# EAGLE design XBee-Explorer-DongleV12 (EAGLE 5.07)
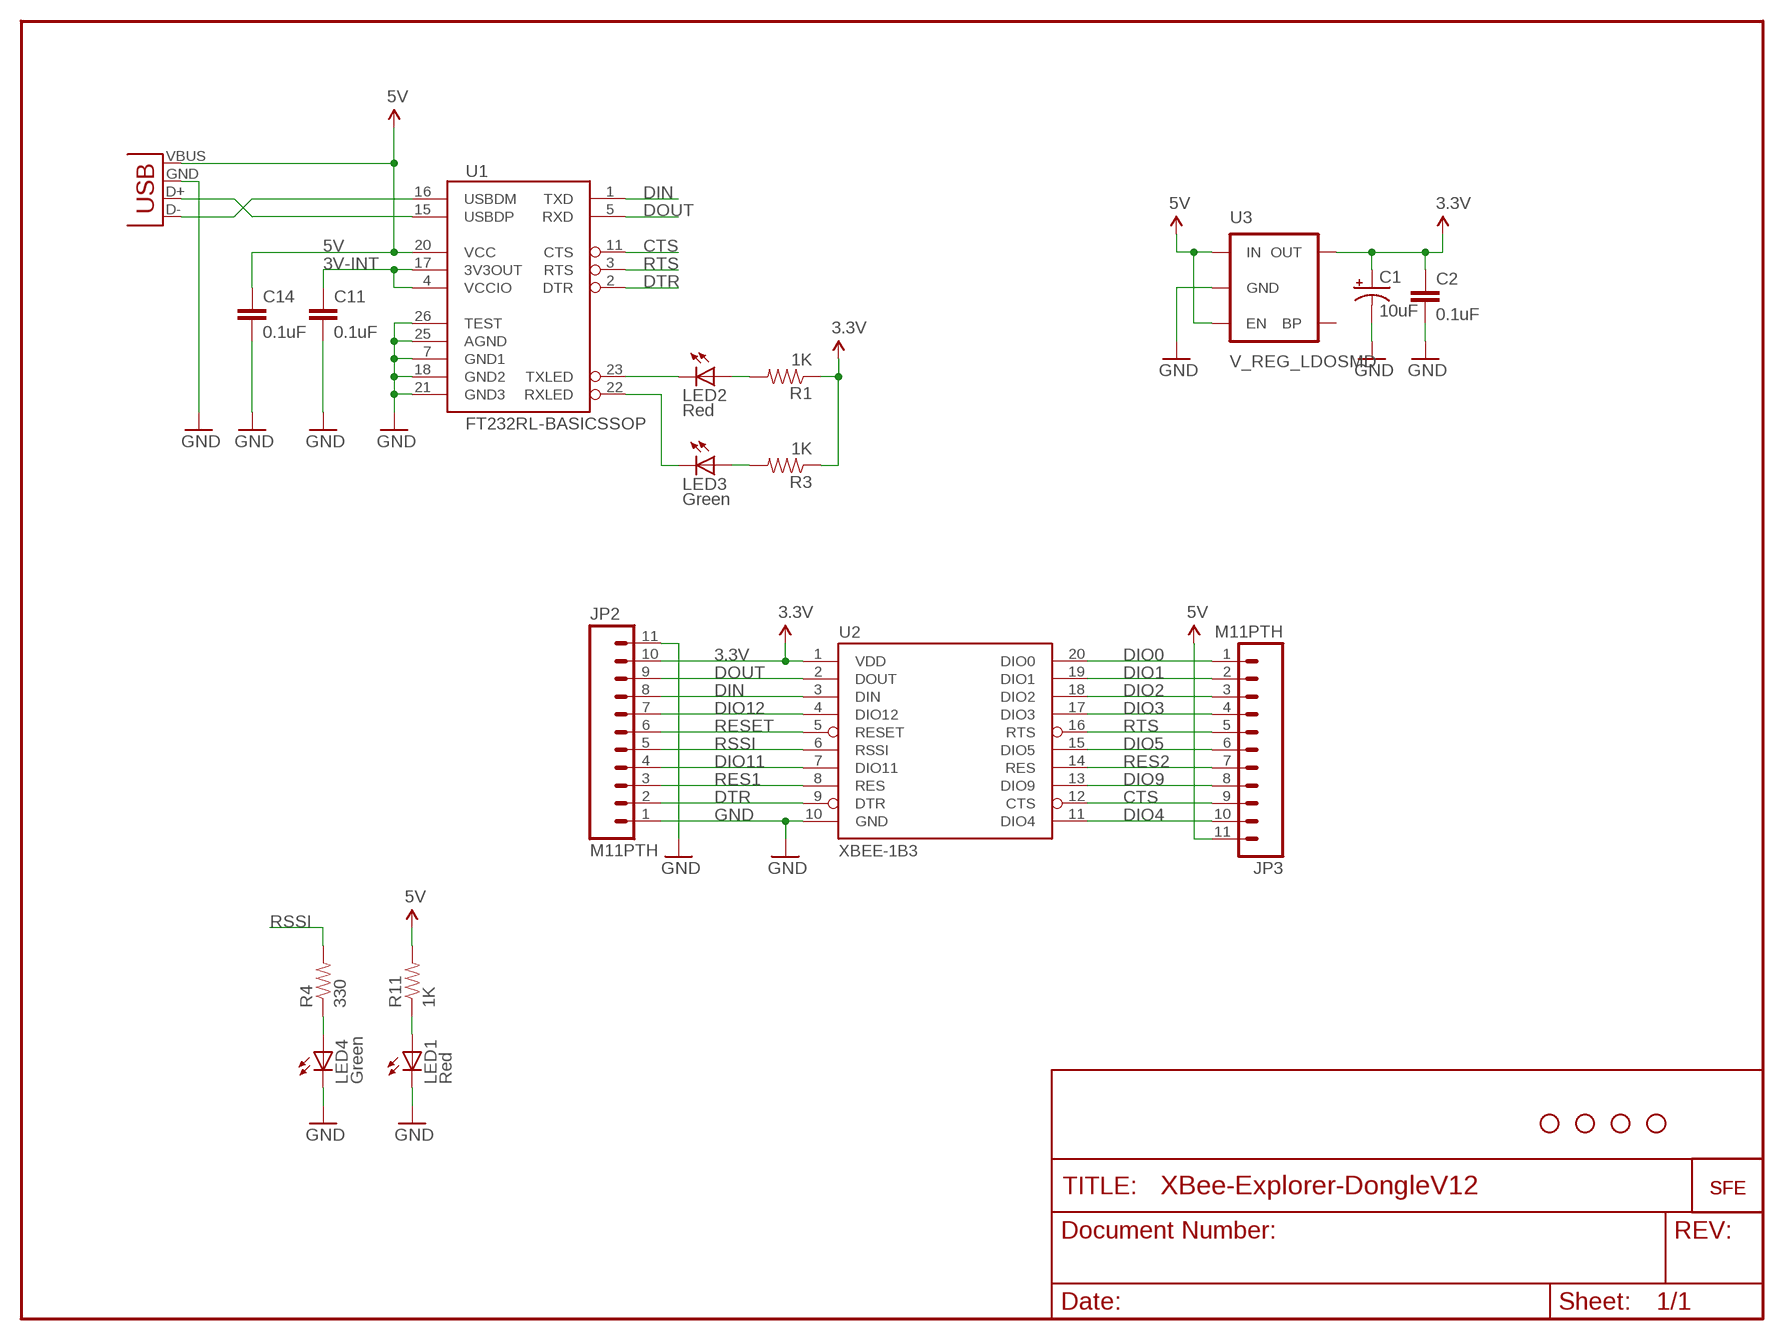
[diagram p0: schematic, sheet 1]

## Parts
C1  10uF  CAP_POL1206  [EIA3216]
C2  0.1uF  CAP0402-CAP  [0402-CAP]
C11  0.1uF  CAP0402-CAP  [0402-CAP]
C14  0.1uF  CAP0402-CAP  [0402-CAP]
JP2  M11PTH  [1X11]
JP3  M11PTH  [1X11]
LED1  Red  LED0603  [LED-0603]
LED2  Red  LED0603  [LED-0603]
LED3  Green  LED0603  [LED-0603]
LED4  Green  LED0603  [LED-0603]
R1  1K  RESISTOR  [0805]
R3  1K  RESISTOR  [0805]
R4  330  RESISTOR0603-RES  [0603-RES]
R11  1K  RESISTOR0603-RES  [0603-RES]
U1  FT232RL-BASICSSOP  [SSOP28DB]
U2  XBEE-1B3  [XBEE-SMD]
U3  V_REG_LDOSMD  [SOT23-5]
U$1  LOGO-SFESK  [SFE-LOGO-FLAME]
U$4  LOGO-SFENEW  [SFE-NEW-WEBLOGO]
U$5  STAND-OFF  [STAND-OFF]
U$9  STAND-OFF  [STAND-OFF]
U$10  STAND-OFF  [STAND-OFF]
U$11  STAND-OFF  [STAND-OFF]
X2  USB-A-H  [USB-A-H]

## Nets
3.3V [vcc]: C1.A(+) C2.1 JP2.10 R1.1 R3.1 U2.1(VDD) U3.5(OUT)
3V-INT [vcc]: C11.1 U1.4(VCCIO) U1.17(3V3OUT)
5V [vcc]: C14.1 JP3.11 R11.2 U1.20(VCC) U3.1(IN) U3.3(EN) X2.VBUS(GND)
CTS: JP3.9 U1.11(CTS) U2.12(CTS)
DIN: JP2.8 U1.1(TXD) U2.3(DIN)
DIO0: JP3.1 U2.20(DIO0)
DIO1: JP3.2 U2.19(DIO1)
DIO2: JP3.3 U2.18(DIO2)
DIO3: JP3.4 U2.17(DIO3)
DIO4: JP3.10 U2.11(DIO4)
DIO5: JP3.6 U2.15(DIO5)
DIO9: JP3.8 U2.13(DIO9)
DIO11: JP2.4 U2.7(DIO11)
DIO12: JP2.7 U2.4(DIO12)
DOUT: JP2.9 U1.5(RXD) U2.2(DOUT)
DTR: JP2.2 U1.2(DTR) U2.9(DTR)
GND [vcc]: C1.C(-) C2.2 C11.2 C14.2 JP2.1 JP2.11 LED1.C LED4.C U1.7(GND1) U1.18(GND2) U1.21(GND3) U1.25(AGND) U1.26(TEST) U2.10(GND) U3.2(GND) X2.GND(VBUS)
N$1: LED2.A R1.2
N$2: LED4.A R4.1
N$3: U1.16(USBDM) X2.D-(D+)
N$4: LED3.A R3.2
N$7: U1.15(USBDP) X2.D+(D-)
N$38: LED1.A R11.1
RES1: JP2.3 U2.8(RES)
RES2: JP3.7 U2.14(RES)
RESET: JP2.6 U2.5(RESET)
RSSI: JP2.5 R4.2 U2.6(RSSI)
RTS: JP3.5 U1.3(RTS) U2.16(RTS)
RXLED: LED3.C U1.22(RXLED)
TXLED: LED2.C U1.23(TXLED)
Unconnected: U3.4(BP)

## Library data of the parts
C1 = SparkFun:CAP_POL: Capacitor Polarized
C2 C11 C14 = SparkFun:CAP: Capacitor
JP2 JP3 = SparkFun:M11: Header 11 Standard 11-pin 0.1" header. Use with straight break away headers (SKU : PRT-00116), right angle break away headers (PRT-00553), swiss pins (PRT-00743), machine pins (PRT-00117), and female headers (PRT-00115).
LED1-LED4 = SparkFun:LED: LEDs
R1 R3 R4 R11 = SparkFun:RESISTOR: Resistor
U1 = SparkFun:FT232RL-BASIC: USB UART This is the simplified version of the FT232RL unit. Only what you need, nothing you don't. Spark Fun Electronics SKU : COM-00650
U2 = SparkFun:XBEE-1
U3 = SparkFun:V_REG_LDO: Voltage Regulator LDO Standard 150mA LDO voltage regulator in SOT-23 layout. Micrel part MIC5205. BP (by-pass) pin is used to lower output noise with 470pF cap.
U$1 U$4 = SparkFun:LOGO-SFE: Spark Fun Electronics PCB Logo
U$5 U$9-U$11 = SparkFun:STAND-OFF: Stand Off
X2 = SparkFun:USB: USB Connectors USB-B-PTH is fully proven SKU : PRT-00139 USB-miniB is fully proven SKU : PRT-00587 USB-A-PCB is untested. USB-A-H is throughly reviewed, but untested. Spark Fun Electronics SKU : PRT-00437 USB-B-SMT is throughly reviewed, but untested. Needs silkscreen touching up. USB-A-S has not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

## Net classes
0 default: width 0.203 mm
1 vcc: width 0.254 mm
2 gnd: width 0.254 mm

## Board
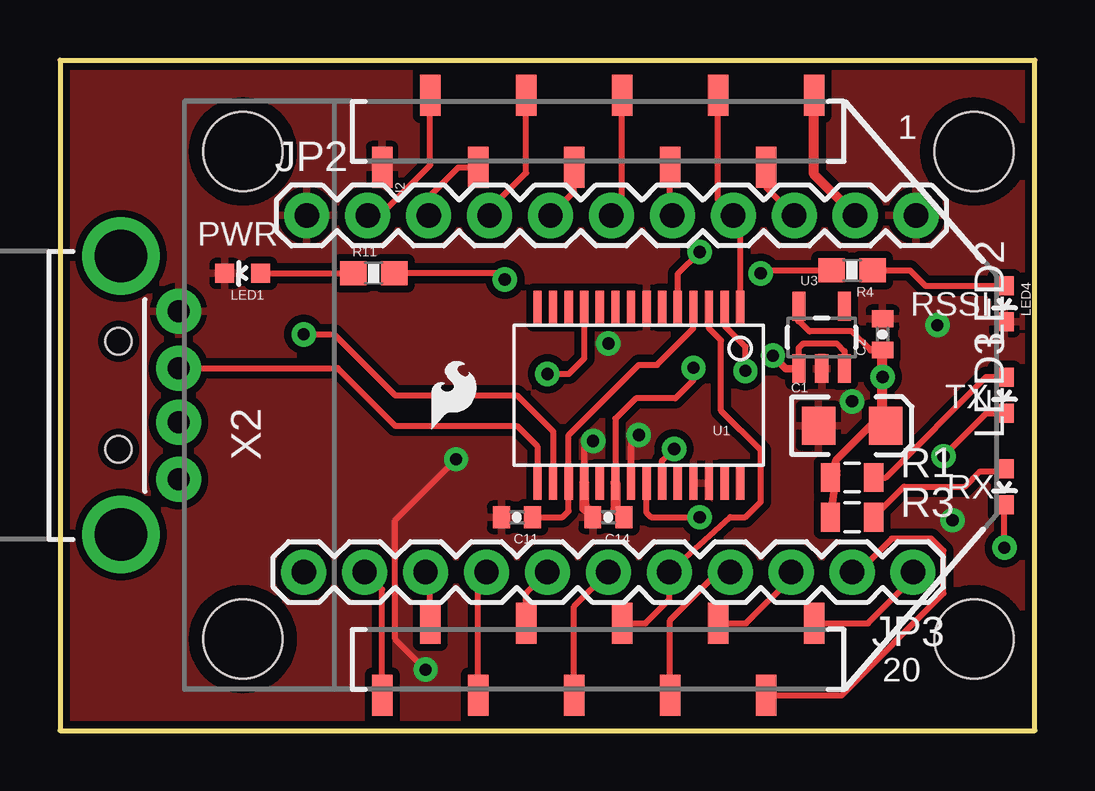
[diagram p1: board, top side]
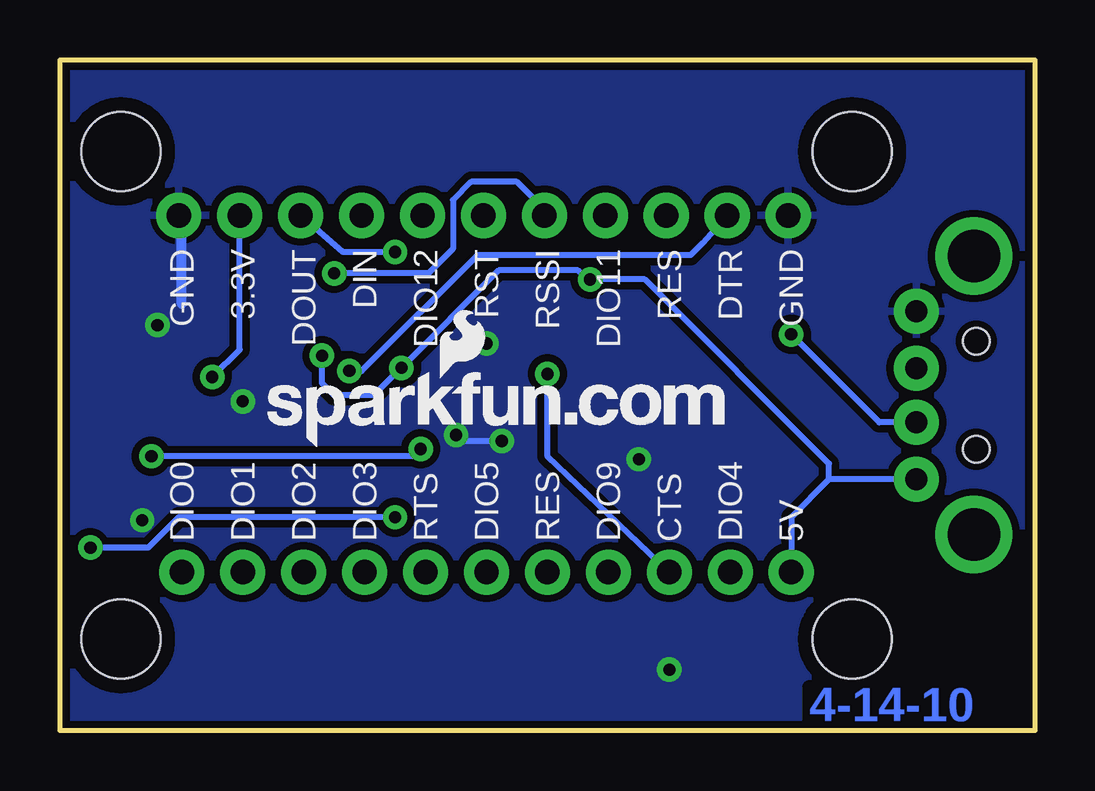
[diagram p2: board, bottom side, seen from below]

Size 40.64 x 27.94 mm. Coordinates in mm from the lower left corner, seen from the top.
Outline: 40.64,0 40.64,27.94 0,27.94 0,0 40.64,0
Copper layers (1*16): Top 0.035mm / dielectric 1.5mm / Bottom 0.035mm
Design rules "SparkFun": minimum track width 8mil, minimum drill 20mil, track to track 8mil, track to pad 8mil, pad to pad 8mil, via to via 8mil, smd to smd 8mil, copper to edge 9mil, drill to drill 8mil, minimum pad ring 12mil, minimum via ring 10mil, stop-mask expansion 4mil, vias tented up to drill 20mil, thermal gap 10mil

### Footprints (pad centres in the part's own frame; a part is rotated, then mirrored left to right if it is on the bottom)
EIA3216 = smd 1.4 x 1.6: A 1.4,0; C -1.4,0
0402-CAP = smd 0.7 x 0.9: 1 -0.65,0; 2 0.65,0
1X11 = drill 1.016 pad 1.88 round: 1 0,0; 2 2.54,0; 3 5.08,0; 4 7.62,0; 5 10.16,0; 6 12.7,0; 7 15.24,0; 8 17.78,0; 9 20.32,0; 10 22.86,0; 11 25.4,0
LED-0603 = smd 0.8 x 0.8: A 0,-0.75; C 0,0.75
0805 = smd 0.8 x 1.2: 1 -0.9,0; 2 0.9,0
0603-RES = smd 1.1 x 1: 1 -0.85,0; 2 0.85,0
SSOP28DB = smd 0.348 x 1.397: 1 -4.225,-3.656; 2 -3.575,-3.656; 3 -2.925,-3.656; 4 -2.275,-3.656; 5 -1.625,-3.656; 6 -0.975,-3.656; 7 -0.325,-3.656; 8 0.325,-3.656; 9 0.975,-3.656; 10 1.625,-3.656; 11 2.275,-3.656; 12 2.925,-3.656; 13 3.575,-3.656; 14 4.225,-3.656; 15 4.225,3.656; 16 3.575,3.656; 17 2.925,3.656; 18 2.275,3.656; 19 1.625,3.656; 20 0.975,3.656; 21 0.325,3.656; 22 -0.325,3.656; 23 -0.975,3.656; 24 -1.625,3.656; 25 -2.275,3.656; 26 -2.925,3.656; 27 -3.575,3.656; 28 -4.225,3.656
XBEE-SMD = smd 1.7 x 0.85: 1 -12.5,20; 2 -9.5,18; 3 -12.5,16; 4 -9.5,14; 5 -12.5,12; 6 -9.5,10; 7 -12.5,8; 8 -9.5,6; 9 -12.5,4; 10 -9.5,2; 11 12.5,2; 12 9.5,4; 13 12.5,6; 14 9.5,8; 15 12.5,10; 16 9.5,12; 17 12.5,14; 18 9.5,16; 19 12.5,18; 20 9.5,20
SOT23-5 = smd 0.55 x 1.2: 1 -0.95,-1.3; 2 0,-1.3; 3 0.95,-1.3; 4 0.95,1.3; 5 -0.95,1.3
STAND-OFF = hole 3.302: 0,0
USB-A-H = drill 0.914 pad 1.88 round: D+ 2.4,1.127; D- 2.4,-1.127; GND 2.4,3.5; VBUS 2.4,-3.5 | drill 2.2 round: GND@1 0,5.8; GND@2 0,-5.8 | hole 1.1: -0.1,2.25; -0.1,-2.25

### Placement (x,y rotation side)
C1  33.02,12.7 0 top
C2  34.29,16.51 90 top
C11  19.05,8.89 180 top
C14  22.86,8.89 180 top
JP2  10.29,21.46 0 top
JP3  35.56,6.6 180 top
LED1  7.62,19.05 90 top
LED2  39.37,13.97 180 top
LED3  39.37,10.16 180 top
LED4  39.37,17.78 180 top
R1  33.02,10.54 0 top
R3  33.02,8.89 0 top
R4  33.02,19.18 180 top
R11  13.08,19.05 0 top
U1  24.13,13.97 180 top
U2  11.43,13.97 270 top
U3  31.75,16.38 0 top
U$1  15.49,12.57 0 top
U$4  32,11.81 0 bottom
U$5  7.62,3.81 0 top
U$9  7.62,24.13 0 top
U$10  38.1,24.13 0 top
U$11  38.1,3.81 0 top
X2  2.54,13.97 0 top

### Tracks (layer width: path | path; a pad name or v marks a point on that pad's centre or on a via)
3.3V  (via drill 0.51)
  Top 0.254: 30.8,17.08 31.24,16.64 33.02,16.64 33.8,15.86
  Top 0.305: R1.1 32.38,10.79 | R1.1 32.37,10.68 32.38,10.67 32.37,10.65 R3.1 | R1.1 32.37,11.29 33.78,12.7 C1.A | C2.1 33.8,15.86 | 30.8,17.08 U3.5
  Top 0.406: 34.29,12.7 C1.A 34.29,12.83 v34.29,14.73 C2.1 | U2.1 31.43,23.18 JP2.10
  Bottom 0.254: JP2.10 33.15,15.88 v34.29,14.73
3V-INT
  Top 0.254: U1.4 26.41,16.75 24.89,15.24 24.13,15.24 21.2,12.31 U1.17 21.2,9.14 20.95,8.89 C11.1
5V  (via drill 0.51)
  Top 0.254: U1.20 23.16,12.99 24,13.84 25.65,13.84 26.41,14.59 v26.41,15.1 | U3.1 30.8,15.94 30.99,16.13 32.38,16.13 32.7,15.81 U3.3 | R11.2 18.29,19.05 v18.54,18.8
  Top 0.305: U3.1 30.26,15.08 v29.72,15.62
  Top 0.406: C14.1 23.5,8.89 23.16,9.23 U1.20 | v26.41,15.11 v26.42,15.11 v26.41,15.1
  Bottom 0.254: 26.41,15.12 22.35,19.18 19.05,19.18 18.67,18.8 v18.54,18.8 16.26,18.8 8.58,11.12 8.58,10.47 | v26.42,15.11 27.56,13.97 29.21,13.97 29.72,14.48 v29.72,15.62 | 8.58,10.47 10.16,8.89 JP3.11 | X2.VBUS 8.58,10.47
  Bottom 0.406: v26.42,15.11 v26.41,15.11 26.41,15.12
CTS  (via drill 0.51)
  Top 0.254: U1.11 21.86,15.51 21.21,14.86 v20.32,14.86 | U2.12 15.43,6.41 JP3.9
  Bottom 0.254: v20.32,14.86 20.32,11.43 JP3.9
DIN
  Top 0.254: U1.1 28.36,21.18 JP2.8 27.43,22.1 U2.3
DIO0
  Top 0.254: U2.20 33.68,4.47 35.56,6.35 JP3.1
DIO1
  Top 0.254: U2.19 32.59,1.47 36.83,5.71 36.83,7.49 36.32,8 34.67,8 33.27,6.6 JP3.2
DIO2
  Top 0.254: U2.18 28.6,4.47 30.48,6.35 JP3.3
DIO3
  Top 0.254: U2.17 25.43,4.6 27.43,6.6 JP3.4
DIO4
  Top 0.254: U2.11 13.43,5.87 JP3.10
DIO5
  Top 0.254: U2.15 21.43,5.17 JP3.6
DIO9
  Top 0.254: U2.13 17.43,6.25 JP3.8
DIO11
  Top 0.254: U2.7 19.43,23.24 17.91,21.72 JP2.4
DIO12
  Top 0.254: U2.4 25.43,21.62 JP2.7
DOUT  (via drill 0.51)
  Top 0.254: U1.5 25.75,19.02 v26.67,19.94 | U2.2 29.43,22.64 JP2.9
  Bottom 0.254: v26.67,19.94 28.83,19.94 JP2.9
DTR  (via drill 0.51)
  Top 0.254: U1.2 27.7,16.87 28.57,16 v28.57,14.99 | U2.9 15.43,23.56 13.34,21.46 JP2.2
  Bottom 0.254: JP2.2 13.84,20.32 14.35,19.81 23.24,19.81 28.07,14.99 v28.57,14.99
GND  (via drill 0.51)
  Top 0.254: 24.13,12.19 23.8,11.87 U1.21 23.8,11.99 v24.13,12.32 24.13,12.7 | U1.18 21.86,11.82 v22.23,12.06 22.1,12.19 | v15.24,2.54 13.97,3.81 13.97,8.76 v16.51,11.3
  Top 0.406: C14.2 22.23,8.89 21.86,9.26 U1.18
  Bottom 0.254: v22.23,12.06 23.88,12.06 v24.13,12.32
  Bottom 0.406: 35.56,17.78 35.56,21.59
  other vias: 37.21,8.76 22.86,16.13 33.02,13.72 36.58,16.89
  pour Bottom (isolate 0.305): 0,27.94 40.64,27.94 40.64,0 0,0
  pour Top (isolate 0.305): 0,27.94 40.64,27.94 40.64,0 0,0
N$1
  Top 0.254: LED2.A 39.37,14.73 38.61,14.73 34.42,10.54 R1.2
N$2
  Top 0.254: LED4.A 36.08,18.53 35.43,19.18 R4.1
N$3  (via drill 0.51)
  Top 0.254: v10.16,16.51 11.43,16.51 13.97,13.97 19.05,13.97 20.55,12.46 U1.16
  Bottom 0.254: X2.D- 6.49,12.84 v10.16,16.51
N$4
  Top 0.254: LED3.A 39.37,10.79 38.35,10.79 37.72,10.16 35.18,10.16 33.91,8.89 R3.2
N$7
  Top 0.254: U1.15 19.94,10.29 | U1.15 19.91,11.85 19.05,12.7 13.97,12.7 12.06,14.61 | U1.15 | 12.06,14.61 11.7,14.97 | X2.D+ 11.57,15.1 12.06,14.61
N$38
  Top 0.254: LED1.A R11.1
RES1
  Top 0.254: U2.8 16.61,23.47 15.37,22.23 JP2.3
RES2
  Top 0.254: U2.14 19.43,5.71 JP3.7
RESET
  Top 0.254: U2.5 23.43,22.16 JP2.6
RSSI  (via drill 0.51)
  Top 0.254: U2.6 21.43,22.45 JP2.5 | R4.2 29.34,19.18 v29.21,19.05
  Bottom 0.254: JP2.5 20.45,21.72 21.59,22.86 23.5,22.86 24.26,22.1 24.26,20.07 25.27,19.05 v29.21,19.05
RTS
  Top 0.254: U1.3 27.05,16.76 27.56,16.26 27.56,13.34 29.21,11.68 29.21,9.53 28.57,8.89 27.94,8.89 JP3.5 25.4,5.46 24.41,4.47 U2.16
RXLED  (via drill 0.51)
  Top 0.254: U1.22 24.45,9.07 24.64,8.89 v26.67,8.89 | v39.37,7.62 LED3.C
  Bottom 0.254: v26.67,8.89 35.69,8.89 36.96,7.62 v39.37,7.62
TXLED  (via drill 0.51)
  Top 0.254: LED2.C 38.62,13.22 v36.83,11.43 | U1.23 25.09,10.32 25.09,11.25 25.58,11.73 v25.6,11.73
  Bottom 0.254: v25.6,11.73 25.91,11.43 v36.83,11.43

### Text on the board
Bottom: 4-14-10
tPlace: 1 | PWR | RSSI | TX | RX | 20
bPlace: GND | DTR | RES | DIO11 | RSSI | RST | DIO12 | DIN | DOUT | 3.3V | GND | 5V | DIO4 | CTS | DIO9 | RES | DIO5 | RTS | DIO3 | DIO2 | DIO1 | DIO0
tValues: XBee Socket Up | DNP | DNP | XBee Socket Up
